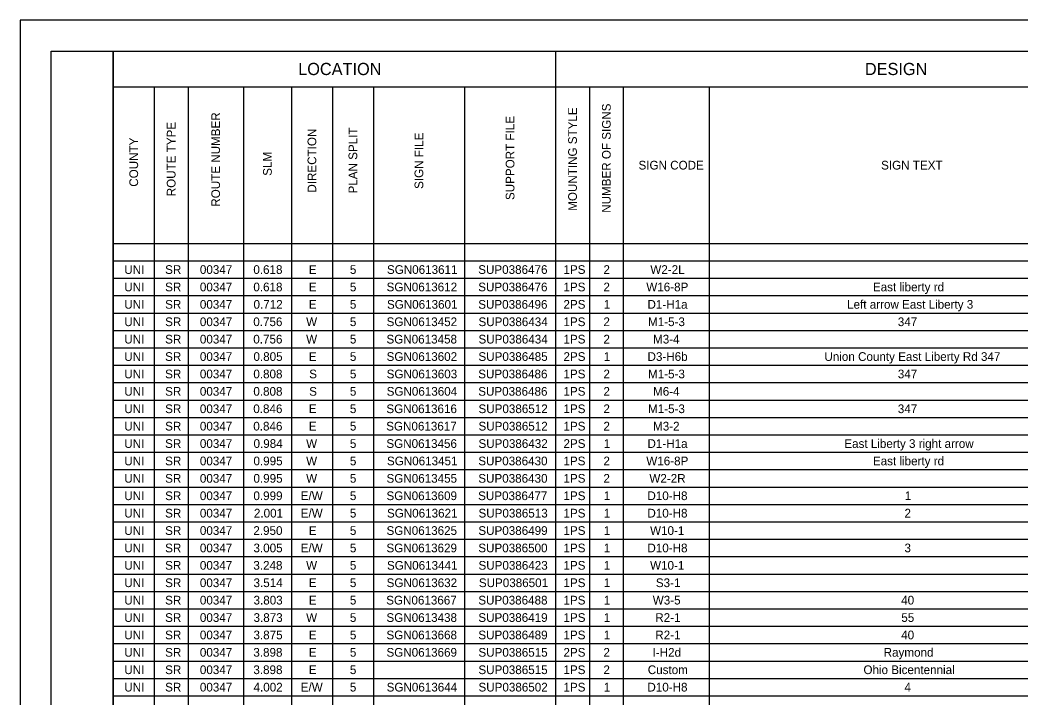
# Model space of a CAD drawing. Extents: x 0 to 34, y 0 to 22.
# Drawn here: x 0 to 16.1, y 11.09 to 22 of the extents above; entities that cross this region are included whole.
import ezdxf

# ---------------------------------------------------------------- set-up
doc = ezdxf.new("R2010")
doc.units = 0
for name, color, linetype in [('SH_Border', 7, 'Continuous'), ('SH_Cut_Line', 7, 'Continuous'), ('SH_Data', 7, 'Continuous'), ('SH_Text', 7, 'Continuous')]:
    doc.layers.add(name, color=color, linetype=linetype)

msp = doc.modelspace()

# ---------------------------------------------------------------- linework, layer by layer
at = {"layer": 'SH_Border'}
for points in [[(0.5, 21.5), (1.5, 21.5), (1.5, 0.5), (0.5, 0.5)], [(1.5, 21.5), (33.5, 21.5), (33.5, 0.5), (1.5, 0.5)]]:
    msp.add_lwpolyline(points, close=True, dxfattribs=at)
at = {"layer": 'SH_Cut_Line'}
msp.add_lwpolyline([(0, 0), (34, 0), (34, 22), (0, 22)], close=True, dxfattribs=at)
at = {"layer": 'SH_Data'}
for p, q in [((1.5, 21.5), (32.004, 21.5)), ((8.615, 21.5), (8.615, 0.764)), ((1.5, 20.924), (28.232, 20.924)), ((1.5, 20.924), (1.5, 0.764)), ((2.159, 20.924), (2.159, 0.764)), ((2.702, 20.924), (2.702, 0.764)), ((3.592, 20.924), (3.592, 0.764)), ((4.366, 20.924), (4.366, 0.764)), ((5.025, 20.924), (5.025, 0.764)), ((5.684, 20.924), (5.684, 0.764)), ((7.149, 20.924), (7.149, 0.764)), ((9.159, 20.924), (9.159, 0.764)), ((9.702, 20.924), (9.702, 0.764)), ((11.086, 20.924), (11.086, 0.764)), ((1.5, 18.404), (32.004, 18.404)), ((1.5, 18.124), (32.004, 18.124)), ((1.5, 17.844), (32.004, 17.844)), ((1.5, 17.564), (32.004, 17.564)), ((1.5, 17.284), (32.004, 17.284)), ((1.5, 17.004), (32.004, 17.004)), ((1.5, 16.724), (32.004, 16.724)), ((1.5, 16.444), (32.004, 16.444)), ((1.5, 16.164), (32.004, 16.164)), ((1.5, 15.884), (32.004, 15.884)), ((1.5, 15.604), (32.004, 15.604)), ((1.5, 15.324), (32.004, 15.324)), ((1.5, 15.044), (32.004, 15.044)), ((1.5, 14.764), (32.004, 14.764)), ((1.5, 14.484), (32.004, 14.484)), ((1.5, 14.204), (32.004, 14.204)), ((1.5, 13.924), (32.004, 13.924)), ((1.5, 13.644), (32.004, 13.644)), ((1.5, 13.364), (32.004, 13.364)), ((1.5, 13.084), (32.004, 13.084)), ((1.5, 12.804), (32.004, 12.804)), ((1.5, 12.524), (32.004, 12.524)), ((1.5, 12.244), (32.004, 12.244)), ((1.5, 11.964), (32.004, 11.964)), ((1.5, 11.684), (32.004, 11.684)), ((1.5, 11.404), (32.004, 11.404)), ((1.5, 11.124), (32.004, 11.124))]:
    msp.add_line(p, q, dxfattribs=at)

# ---------------------------------------------------------------- texts
at = {"layer": 'SH_Text'}
for s, height, p in [('LOCATION', 0.196, (4.474, 21.114)), ('DESIGN', 0.196, (13.589, 21.114)), ('SIGN CODE', 0.14, (9.948, 19.594)), ('SIGN TEXT', 0.14, (13.85, 19.594)), ('UNI', 0.14, (1.677, 17.914)), ('SR', 0.14, (2.334, 17.914)), ('00347', 0.14, (2.893, 17.914)), ('0.618', 0.14, (3.753, 17.914)), ('E', 0.14, (4.645, 17.914)), ('5', 0.14, (5.306, 17.914)), ('SGN0613611', 0.14, (5.902, 17.914)), ('SUP0386476', 0.14, (7.37, 17.914)), ('1PS', 0.14, (8.741, 17.914)), ('2', 0.14, (9.384, 17.914)), ('W2-2L', 0.14, (10.138, 17.914)), ('UNI', 0.14, (1.677, 17.634)), ('SR', 0.14, (2.334, 17.634)), ('00347', 0.14, (2.893, 17.634)), ('0.618', 0.14, (3.753, 17.634)), ('E', 0.14, (4.645, 17.634)), ('5', 0.14, (5.306, 17.634)), ('SGN0613612', 0.14, (5.896, 17.634)), ('SUP0386476', 0.14, (7.37, 17.634)), ('1PS', 0.14, (8.741, 17.634)), ('2', 0.14, (9.384, 17.634)), ('W16-8P', 0.14, (10.073, 17.634)), ('East liberty rd', 0.14, (13.718, 17.634)), ('UNI', 0.14, (1.677, 17.354)), ('SR', 0.14, (2.334, 17.354)), ('00347', 0.14, (2.893, 17.354)), ('0.712', 0.14, (3.756, 17.354)), ('E', 0.14, (4.645, 17.354)), ('5', 0.14, (5.306, 17.354)), ('SGN0613601', 0.14, (5.902, 17.354)), ('SUP0386496', 0.14, (7.37, 17.354)), ('2PS', 0.14, (8.741, 17.354)), ('1', 0.14, (9.389, 17.354)), ('D1-H1a', 0.14, (10.092, 17.354)), ('Left arrow East Liberty 3', 0.14, (13.303, 17.354)), ('UNI', 0.14, (1.677, 17.074)), ('SR', 0.14, (2.334, 17.074)), ('00347', 0.14, (2.893, 17.074)), ('0.756', 0.14, (3.752, 17.074)), ('W', 0.14, (4.602, 17.074)), ('5', 0.14, (5.306, 17.074)), ('SGN0613452', 0.14, (5.896, 17.074)), ('SUP0386434', 0.14, (7.374, 17.074)), ('1PS', 0.14, (8.741, 17.074)), ('2', 0.14, (9.384, 17.074)), ('M1-5-3', 0.14, (10.101, 17.074)), ('347', 0.14, (14.119, 17.074)), ('UNI', 0.14, (1.677, 16.794)), ('SR', 0.14, (2.334, 16.794)), ('00347', 0.14, (2.893, 16.794)), ('0.756', 0.14, (3.752, 16.794)), ('W', 0.14, (4.602, 16.794)), ('5', 0.14, (5.306, 16.794)), ('SGN0613458', 0.14, (5.894, 16.794)), ('SUP0386434', 0.14, (7.374, 16.794)), ('1PS', 0.14, (8.741, 16.794)), ('2', 0.14, (9.384, 16.794)), ('M3-4', 0.14, (10.182, 16.794)), ('UNI', 0.14, (1.677, 16.514)), ('SR', 0.14, (2.334, 16.514)), ('00347', 0.14, (2.893, 16.514)), ('0.805', 0.14, (3.755, 16.514)), ('E', 0.14, (4.645, 16.514)), ('5', 0.14, (5.306, 16.514)), ('SGN0613602', 0.14, (5.896, 16.514)), ('SUP0386485', 0.14, (7.373, 16.514)), ('2PS', 0.14, (8.741, 16.514)), ('1', 0.14, (9.389, 16.514)), ('D3-H6b', 0.14, (10.093, 16.514)), ('Union County East Liberty Rd 347', 0.14, (12.938, 16.514)), ('UNI', 0.14, (1.677, 16.234)), ('SR', 0.14, (2.334, 16.234)), ('00347', 0.14, (2.893, 16.234)), ('0.808', 0.14, (3.753, 16.234)), ('S', 0.14, (4.651, 16.234)), ('5', 0.14, (5.306, 16.234)), ('SGN0613603', 0.14, (5.897, 16.234)), ('SUP0386486', 0.14, (7.37, 16.234)), ('1PS', 0.14, (8.741, 16.234)), ('2', 0.14, (9.384, 16.234)), ('M1-5-3', 0.14, (10.101, 16.234)), ('347', 0.14, (14.119, 16.234)), ('UNI', 0.14, (1.677, 15.954)), ('SR', 0.14, (2.334, 15.954)), ('00347', 0.14, (2.893, 15.954)), ('0.808', 0.14, (3.753, 15.954)), ('S', 0.14, (4.651, 15.954)), ('5', 0.14, (5.306, 15.954)), ('SGN0613604', 0.14, (5.897, 15.954)), ('SUP0386486', 0.14, (7.37, 15.954)), ('1PS', 0.14, (8.741, 15.954)), ('2', 0.14, (9.384, 15.954)), ('M6-4', 0.14, (10.182, 15.954)), ('UNI', 0.14, (1.677, 15.674)), ('SR', 0.14, (2.334, 15.674)), ('00347', 0.14, (2.893, 15.674)), ('0.846', 0.14, (3.752, 15.674)), ('E', 0.14, (4.645, 15.674)), ('5', 0.14, (5.306, 15.674)), ('SGN0613616', 0.14, (5.893, 15.674)), ('SUP0386512', 0.14, (7.374, 15.674)), ('1PS', 0.14, (8.741, 15.674)), ('2', 0.14, (9.384, 15.674)), ('M1-5-3', 0.14, (10.101, 15.674)), ('347', 0.14, (14.119, 15.674)), ('UNI', 0.14, (1.677, 15.394)), ('SR', 0.14, (2.334, 15.394)), ('00347', 0.14, (2.893, 15.394)), ('0.846', 0.14, (3.752, 15.394)), ('E', 0.14, (4.645, 15.394)), ('5', 0.14, (5.306, 15.394)), ('SGN0613617', 0.14, (5.89, 15.394)), ('SUP0386512', 0.14, (7.374, 15.394)), ('1PS', 0.14, (8.741, 15.394)), ('2', 0.14, (9.384, 15.394)), ('M3-2', 0.14, (10.182, 15.394)), ('UNI', 0.14, (1.677, 15.114)), ('SR', 0.14, (2.334, 15.114)), ('00347', 0.14, (2.893, 15.114)), ('0.984', 0.14, (3.756, 15.114)), ('W', 0.14, (4.602, 15.114)), ('5', 0.14, (5.306, 15.114)), ('SGN0613456', 0.14, (5.893, 15.114)), ('SUP0386432', 0.14, (7.374, 15.114)), ('2PS', 0.14, (8.741, 15.114)), ('1', 0.14, (9.389, 15.114)), ('D1-H1a', 0.14, (10.092, 15.114)), ('East Liberty 3 right arrow', 0.14, (13.258, 15.114)), ('UNI', 0.14, (1.677, 14.834)), ('SR', 0.14, (2.334, 14.834)), ('00347', 0.14, (2.893, 14.834)), ('0.995', 0.14, (3.755, 14.834)), ('W', 0.14, (4.602, 14.834)), ('5', 0.14, (5.306, 14.834)), ('SGN0613451', 0.14, (5.902, 14.834)), ('SUP0386430', 0.14, (7.371, 14.834)), ('1PS', 0.14, (8.741, 14.834)), ('2', 0.14, (9.384, 14.834)), ('W16-8P', 0.14, (10.073, 14.834)), ('East liberty rd', 0.14, (13.718, 14.834)), ('UNI', 0.14, (1.677, 14.554)), ('SR', 0.14, (2.334, 14.554)), ('00347', 0.14, (2.893, 14.554)), ('0.995', 0.14, (3.755, 14.554)), ('W', 0.14, (4.602, 14.554)), ('5', 0.14, (5.306, 14.554)), ('SGN0613455', 0.14, (5.895, 14.554)), ('SUP0386430', 0.14, (7.371, 14.554)), ('1PS', 0.14, (8.741, 14.554)), ('2', 0.14, (9.384, 14.554)), ('W2-2R', 0.14, (10.123, 14.554)), ('UNI', 0.14, (1.677, 14.274)), ('SR', 0.14, (2.334, 14.274)), ('00347', 0.14, (2.893, 14.274)), ('0.999', 0.14, (3.754, 14.274)), ('E/W', 0.14, (4.515, 14.274)), ('5', 0.14, (5.306, 14.274)), ('SGN0613609', 0.14, (5.894, 14.274)), ('SUP0386477', 0.14, (7.368, 14.274)), ('1PS', 0.14, (8.741, 14.274)), ('1', 0.14, (9.389, 14.274)), ('D10-H8', 0.14, (10.091, 14.274)), ('1', 0.14, (14.232, 14.274)), ('UNI', 0.14, (1.677, 13.994)), ('SR', 0.14, (2.334, 13.994)), ('00347', 0.14, (2.893, 13.994)), ('2.001', 0.14, (3.762, 13.994)), ('E/W', 0.14, (4.515, 13.994)), ('5', 0.14, (5.306, 13.994)), ('SGN0613621', 0.14, (5.902, 13.994)), ('SUP0386513', 0.14, (7.374, 13.994)), ('1PS', 0.14, (8.741, 13.994)), ('1', 0.14, (9.389, 13.994)), ('D10-H8', 0.14, (10.091, 13.994)), ('2', 0.14, (14.226, 13.994)), ('UNI', 0.14, (1.677, 13.714)), ('SR', 0.14, (2.334, 13.714)), ('00347', 0.14, (2.893, 13.714)), ('2.950', 0.14, (3.753, 13.714)), ('E', 0.14, (4.645, 13.714)), ('5', 0.14, (5.306, 13.714)), ('SGN0613625', 0.14, (5.895, 13.714)), ('SUP0386499', 0.14, (7.372, 13.714)), ('1PS', 0.14, (8.741, 13.714)), ('1', 0.14, (9.389, 13.714)), ('W10-1', 0.14, (10.134, 13.714)), ('UNI', 0.14, (1.677, 13.434)), ('SR', 0.14, (2.334, 13.434)), ('00347', 0.14, (2.893, 13.434)), ('3.005', 0.14, (3.755, 13.434)), ('E/W', 0.14, (4.515, 13.434)), ('5', 0.14, (5.306, 13.434)), ('SGN0613629', 0.14, (5.894, 13.434)), ('SUP0386500', 0.14, (7.371, 13.434)), ('1PS', 0.14, (8.741, 13.434)), ('1', 0.14, (9.389, 13.434)), ('D10-H8', 0.14, (10.091, 13.434)), ('3', 0.14, (14.226, 13.434)), ('UNI', 0.14, (1.677, 13.154)), ('SR', 0.14, (2.334, 13.154)), ('00347', 0.14, (2.893, 13.154)), ('3.248', 0.14, (3.753, 13.154)), ('W', 0.14, (4.602, 13.154)), ('5', 0.14, (5.306, 13.154)), ('SGN0613441', 0.14, (5.902, 13.154)), ('SUP0386423', 0.14, (7.374, 13.154)), ('1PS', 0.14, (8.741, 13.154)), ('1', 0.14, (9.389, 13.154)), ('W10-1', 0.14, (10.134, 13.154)), ('UNI', 0.14, (1.677, 12.874)), ('SR', 0.14, (2.334, 12.874)), ('00347', 0.14, (2.893, 12.874)), ('3.514', 0.14, (3.756, 12.874)), ('E', 0.14, (4.645, 12.874)), ('5', 0.14, (5.306, 12.874)), ('SGN0613632', 0.14, (5.896, 12.874)), ('SUP0386501', 0.14, (7.38, 12.874)), ('1PS', 0.14, (8.741, 12.874)), ('1', 0.14, (9.389, 12.874)), ('S3-1', 0.14, (10.227, 12.874)), ('UNI', 0.14, (1.677, 12.594)), ('SR', 0.14, (2.334, 12.594)), ('00347', 0.14, (2.893, 12.594)), ('3.803', 0.14, (3.756, 12.594)), ('E', 0.14, (4.645, 12.594)), ('5', 0.14, (5.306, 12.594)), ('SGN0613667', 0.14, (5.89, 12.594)), ('SUP0386488', 0.14, (7.371, 12.594)), ('1PS', 0.14, (8.741, 12.594)), ('1', 0.14, (9.389, 12.594)), ('W3-5', 0.14, (10.177, 12.594)), ('40', 0.14, (14.173, 12.594)), ('UNI', 0.14, (1.677, 12.314)), ('SR', 0.14, (2.334, 12.314)), ('00347', 0.14, (2.893, 12.314)), ('3.873', 0.14, (3.756, 12.314)), ('W', 0.14, (4.602, 12.314)), ('5', 0.14, (5.306, 12.314)), ('SGN0613438', 0.14, (5.894, 12.314)), ('SUP0386419', 0.14, (7.372, 12.314)), ('1PS', 0.14, (8.741, 12.314)), ('1', 0.14, (9.389, 12.314)), ('R2-1', 0.14, (10.218, 12.314)), ('55', 0.14, (14.175, 12.314)), ('UNI', 0.14, (1.677, 12.034)), ('SR', 0.14, (2.334, 12.034)), ('00347', 0.14, (2.893, 12.034)), ('3.875', 0.14, (3.755, 12.034)), ('E', 0.14, (4.645, 12.034)), ('5', 0.14, (5.306, 12.034)), ('SGN0613668', 0.14, (5.894, 12.034)), ('SUP0386489', 0.14, (7.372, 12.034)), ('1PS', 0.14, (8.741, 12.034)), ('1', 0.14, (9.389, 12.034)), ('R2-1', 0.14, (10.218, 12.034)), ('40', 0.14, (14.173, 12.034)), ('UNI', 0.14, (1.677, 11.754)), ('SR', 0.14, (2.334, 11.754)), ('00347', 0.14, (2.893, 11.754)), ('3.898', 0.14, (3.753, 11.754)), ('E', 0.14, (4.645, 11.754)), ('5', 0.14, (5.306, 11.754)), ('SGN0613669', 0.14, (5.894, 11.754)), ('SUP0386515', 0.14, (7.373, 11.754)), ('2PS', 0.14, (8.741, 11.754)), ('2', 0.14, (9.384, 11.754)), ('I-H2d', 0.14, (10.174, 11.754)), ('Raymond', 0.14, (13.891, 11.754)), ('UNI', 0.14, (1.677, 11.474)), ('SR', 0.14, (2.334, 11.474)), ('00347', 0.14, (2.893, 11.474)), ('3.898', 0.14, (3.753, 11.474)), ('E', 0.14, (4.645, 11.474)), ('5', 0.14, (5.306, 11.474)), ('SUP0386515', 0.14, (7.373, 11.474)), ('1PS', 0.14, (8.741, 11.474)), ('2', 0.14, (9.384, 11.474)), ('Custom', 0.14, (10.097, 11.474)), ('Ohio Bicentennial', 0.14, (13.566, 11.474)), ('UNI', 0.14, (1.677, 11.194)), ('SR', 0.14, (2.334, 11.194)), ('00347', 0.14, (2.893, 11.194)), ('4.002', 0.14, (3.756, 11.194)), ('E/W', 0.14, (4.515, 11.194)), ('5', 0.14, (5.306, 11.194)), ('SGN0613644', 0.14, (5.897, 11.194)), ('SUP0386502', 0.14, (7.374, 11.194)), ('1PS', 0.14, (8.741, 11.194)), ('1', 0.14, (9.389, 11.194)), ('D10-H8', 0.14, (10.091, 11.194)), ('4', 0.14, (14.226, 11.194))]:
    msp.add_text(s, height=height, dxfattribs=at).set_placement(p)
for s, p in [('NUMBER OF SIGNS', (9.501, 18.898)), ('ROUTE NUMBER', (3.217, 18.996)), ('SUPPORT FILE', (7.952, 19.103)), ('MOUNTING STYLE', (8.957, 18.93)), ('ROUTE TYPE', (2.501, 19.164)), ('DIRECTION', (4.765, 19.222)), ('PLAN SPLIT', (5.424, 19.209)), ('SIGN FILE', (6.486, 19.282)), ('COUNTY', (1.899, 19.317)), ('SLM', (4.049, 19.493))]:
    msp.add_text(s, height=0.14, rotation=90, dxfattribs=at).set_placement(p)

doc.saveas('drawing.dxf')
